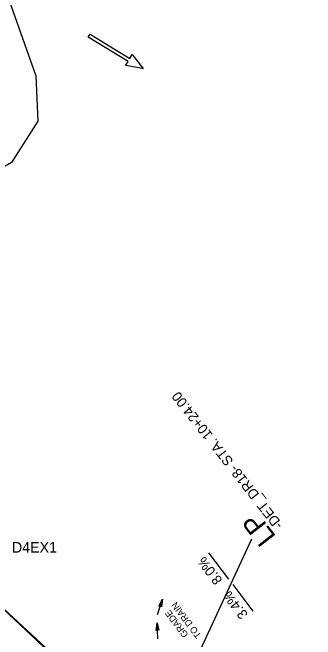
# Model space of a CAD drawing. Extents: x 465700 to 483515, y 488970 to 507540.
# Drawn here: x 476667 to 476894.9, y 500690.3 to 501161.6 of the extents above; entities that cross this region are included whole.
import ezdxf

# ---------------------------------------------------------------- set-up
doc = ezdxf.new("R2010")
doc.units = 0
for name, color, linetype in [('Default', 7, 'Continuous'), ('Exist Plan Preparation Drainage Flow Arrows', 7, 'Continuous'), ('Exist Plan Preparation Watershed Blue', 7, 'Continuous'), ('Prop Plan Preparation Grade to Drain Arrows CELL', 7, 'Continuous'), ('Prop Plan Preparation Grade to Drain Arrows Label', 7, 'Continuous'), ('Prop Plan Preparation Sag', 7, 'Continuous'), ('Prop Plan Preparation Sag Label', 7, 'Continuous'), ('Scratch_Level_8', 7, 'Continuous')]:
    doc.layers.add(name, color=color, linetype=linetype)

# ---------------------------------------------------------------- blocks, each defined once
blk = doc.blocks.new('Existing ground flow arrow')
at = {"layer": 'Default'}
blk.add_line((2.5, -4.33), (2.5, -4.33), dxfattribs=at)
blk.add_lwpolyline([(-1.29, -47.2), (-1.28, -12.53), (-4.77, -12.53), (-1.65, -4.33), (0, 0), (1.65, -4.33), (4.78, -12.53), (1.28, -12.52), (1.29, -47.19), (0, -47.2)], close=True, dxfattribs=at)

msp = doc.modelspace()

# ---------------------------------------------------------------- linework, layer by layer
at = {"layer": 'Exist Plan Preparation Watershed Blue'}
for points in [[(476921.2, 501693.96), (476873.97, 501665.49), (476797.54, 501630.58), (476778.04, 501586.57), (476684.08, 501524.02), (476617.13, 501430.2), (476608.09, 501344.67), (476632.2, 501297.34), (476652.85, 501202.84), (476684.48, 501113.94), (476686.07, 501079.86), (476666.3, 501048.93), (476630.01, 501028.21), (476577.87, 501021.26), (476528.03, 501006.59), (476466.6, 500992.22), (476420.26, 500966.99), (476486.96, 500889.51), (476555.03, 500816.27), (476625.62, 500745.44), (476698.65, 500677.13), (476726.48, 500652.21), (476834.31, 500555.52), (476965.29, 500641)], [(476922.43, 500477.32), (476847.82, 500543.91), (476773.22, 500610.51), (476698.65, 500677.13), (476625.62, 500745.44), (476555.03, 500816.27), (476486.96, 500889.51), (476420.26, 500966.99), (476358.7, 501042.92), (476298.67, 501122.89), (476241.47, 501204.91)], [(476965.29, 500641), (476834.31, 500555.52), (476726.48, 500652.21), (476625.62, 500745.44), (476555.03, 500816.27), (476486.96, 500889.51), (476420.26, 500966.99), (476358.7, 501042.92), (476298.67, 501122.89), (476241.47, 501204.91)], [(476652.85, 501202.84), (476684.48, 501113.94), (476686.07, 501079.86), (476666.3, 501048.93), (476630.01, 501028.21), (476577.87, 501021.26), (476528.03, 501006.59), (476497.08, 501000.21), (476482.89, 500996.49), (476466.6, 500992.22), (476455.71, 500986.82), (476443.7, 500979.93), (476439.14, 500977.28), (476420.26, 500966.99), (476358.7, 501042.92), (476298.67, 501122.89), (476241.47, 501204.91)]]:
    msp.add_lwpolyline(points, dxfattribs=at)
at = {"layer": 'Prop Plan Preparation Grade to Drain Arrows CELL'}
for p, q in [((476776.13, 500709.17), (476779.73, 500720.62)), ((476776.16, 500690.88), (476775.81, 500702.87))]:
    msp.add_line(p, q, dxfattribs=at)
for points in [[(476777.11, 500715.46), (476779.73, 500720.62), (476778.92, 500714.89), (476778.23, 500715.85)], [(476775.02, 500697.14), (476775.81, 500702.87), (476776.92, 500697.19), (476775.95, 500697.87)]]:
    msp.add_lwpolyline(points, close=True, dxfattribs=at)
at = {"layer": 'Prop Plan Preparation Sag'}
msp.add_line((476783.98, 500630.18), (476846.88, 500765.92), dxfattribs=at)
at = {"layer": 'Prop Plan Preparation Sag Label'}
for p, q in [((476829.65, 500735.55), (476814.56, 500755.48)), ((476832.67, 500731.56), (476847.75, 500711.63))]:
    msp.add_line(p, q, dxfattribs=at)

# ---------------------------------------------------------------- block references
at = {"layer": 'Exist Plan Preparation Drainage Flow Arrows', "xscale": 1.0124070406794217, "yscale": 1.0124070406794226, "rotation": -121.44630418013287}
msp.add_blockref('Existing ground flow arrow', (476765.34, 501119.35), dxfattribs=at)

# ---------------------------------------------------------------- texts
at = {"layer": 'Prop Plan Preparation Grade to Drain Arrows Label'}
for s, p in [('TO DRAIN', (476809.42, 500693.49)), ('GRADE ', (476799.56, 500694.08))]:
    msp.add_text(s, height=5, rotation=127.1208, dxfattribs=at).set_placement(p)
at = {"layer": 'Prop Plan Preparation Sag Label'}
for s, height, rotation, p in [('-DET_DR18- STA. 10+24.00', 7.5, 128.006, (476870.84, 500776.62)), ('LP', 15, 128.0094, (476865.63, 500767.8)), ('8.0%', 7.5, 127.1236, (476825.25, 500735.01)), ('3.4%', 7.5, 127.1236, (476844.43, 500709.22))]:
    msp.add_text(s, height=height, rotation=rotation, dxfattribs=at).set_placement(p)
at = {"layer": 'Scratch_Level_8'}
msp.add_text('D4EX1', height=8, dxfattribs=at).set_placement((476666.52, 500755.59))

doc.saveas('drawing.dxf')
